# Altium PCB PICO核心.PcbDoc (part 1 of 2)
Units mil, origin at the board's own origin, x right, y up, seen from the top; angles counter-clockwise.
Board outline 3937.01 x 3543.31 mil, 4 copper layers (Top Layer, GND, VCC, Bottom Layer), stack 23.756 mil thick; 147 components, 105 nets, 477 pads, 202 vias.
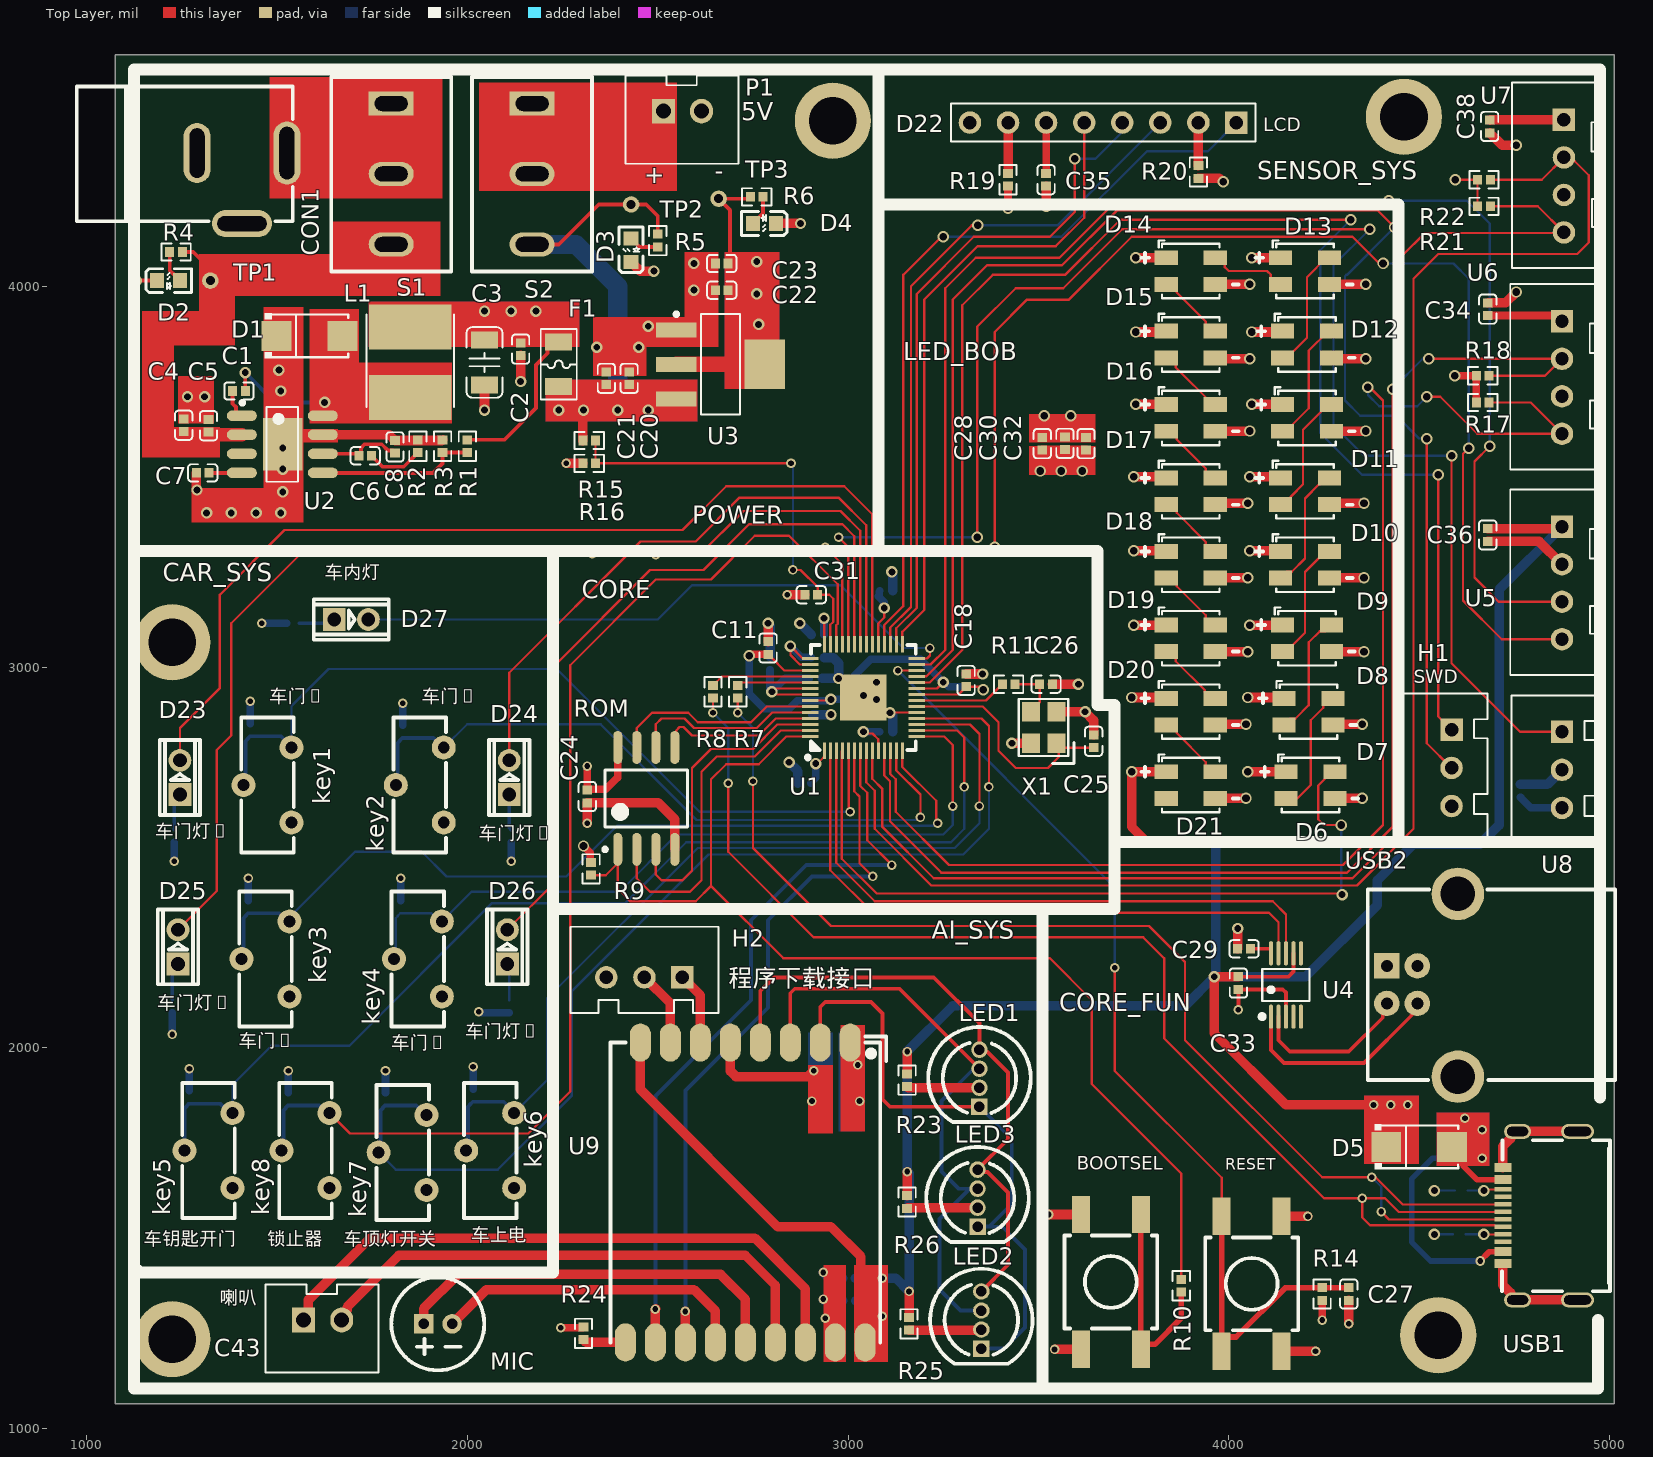
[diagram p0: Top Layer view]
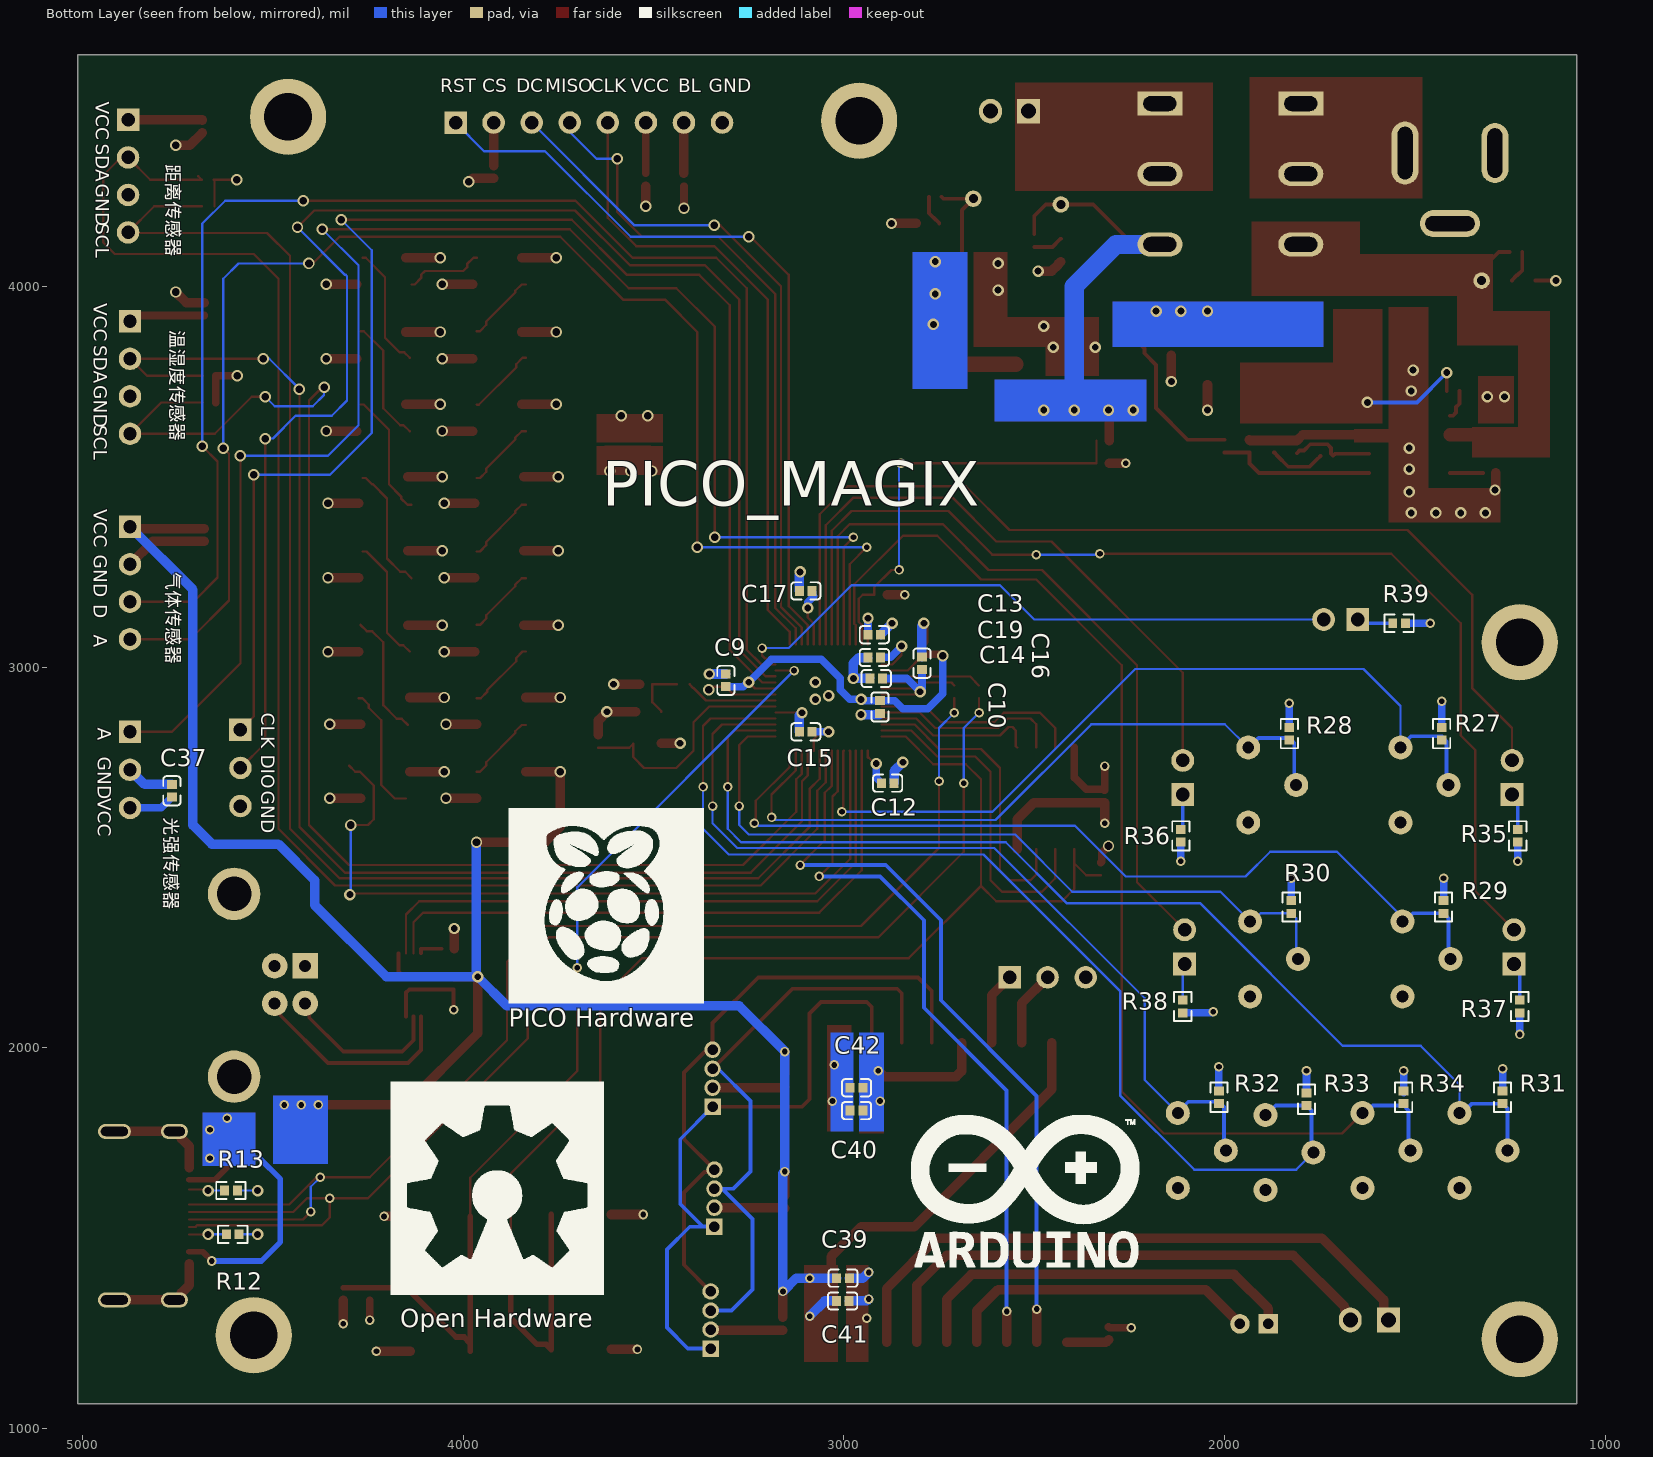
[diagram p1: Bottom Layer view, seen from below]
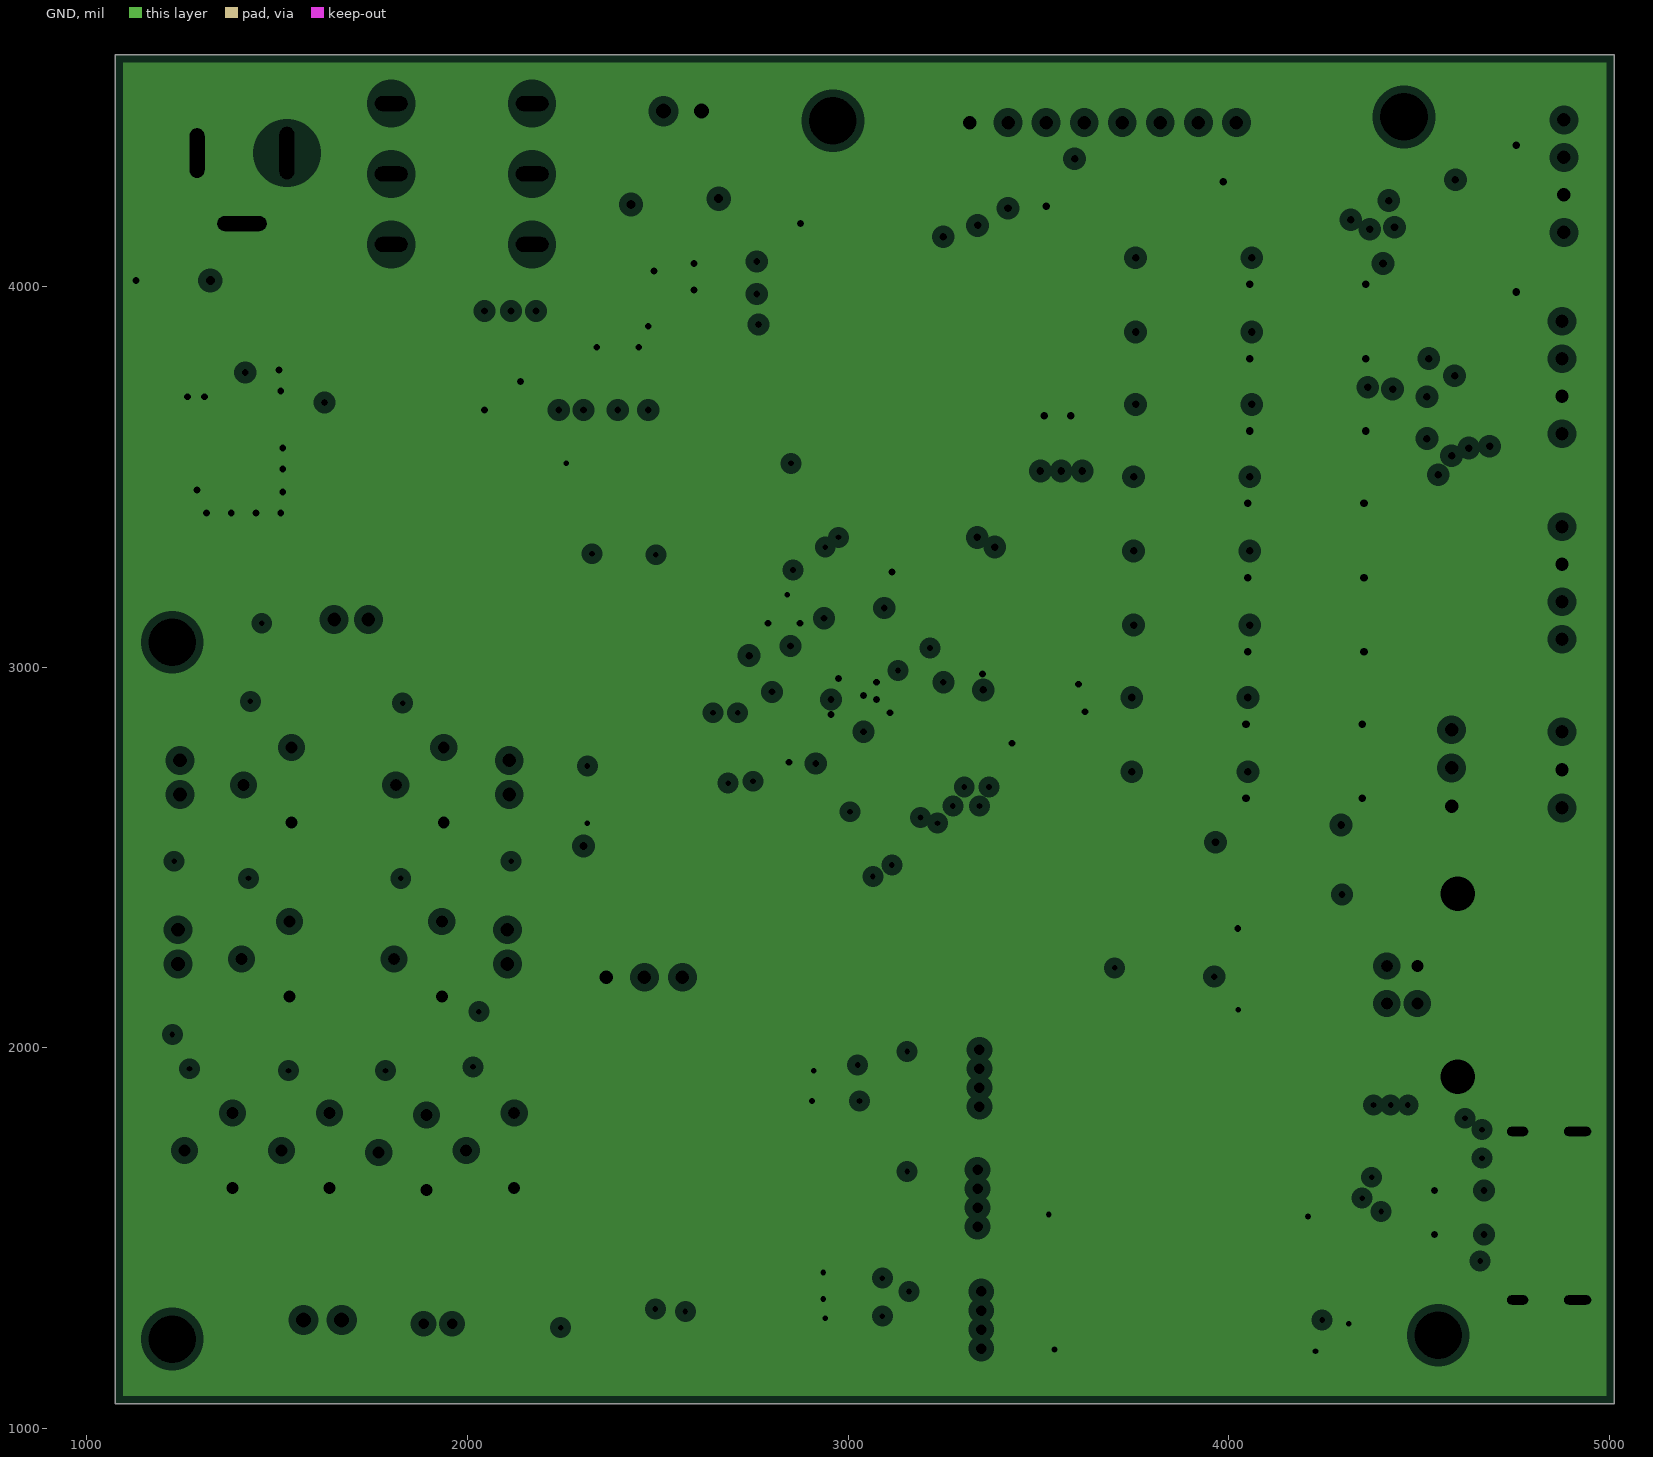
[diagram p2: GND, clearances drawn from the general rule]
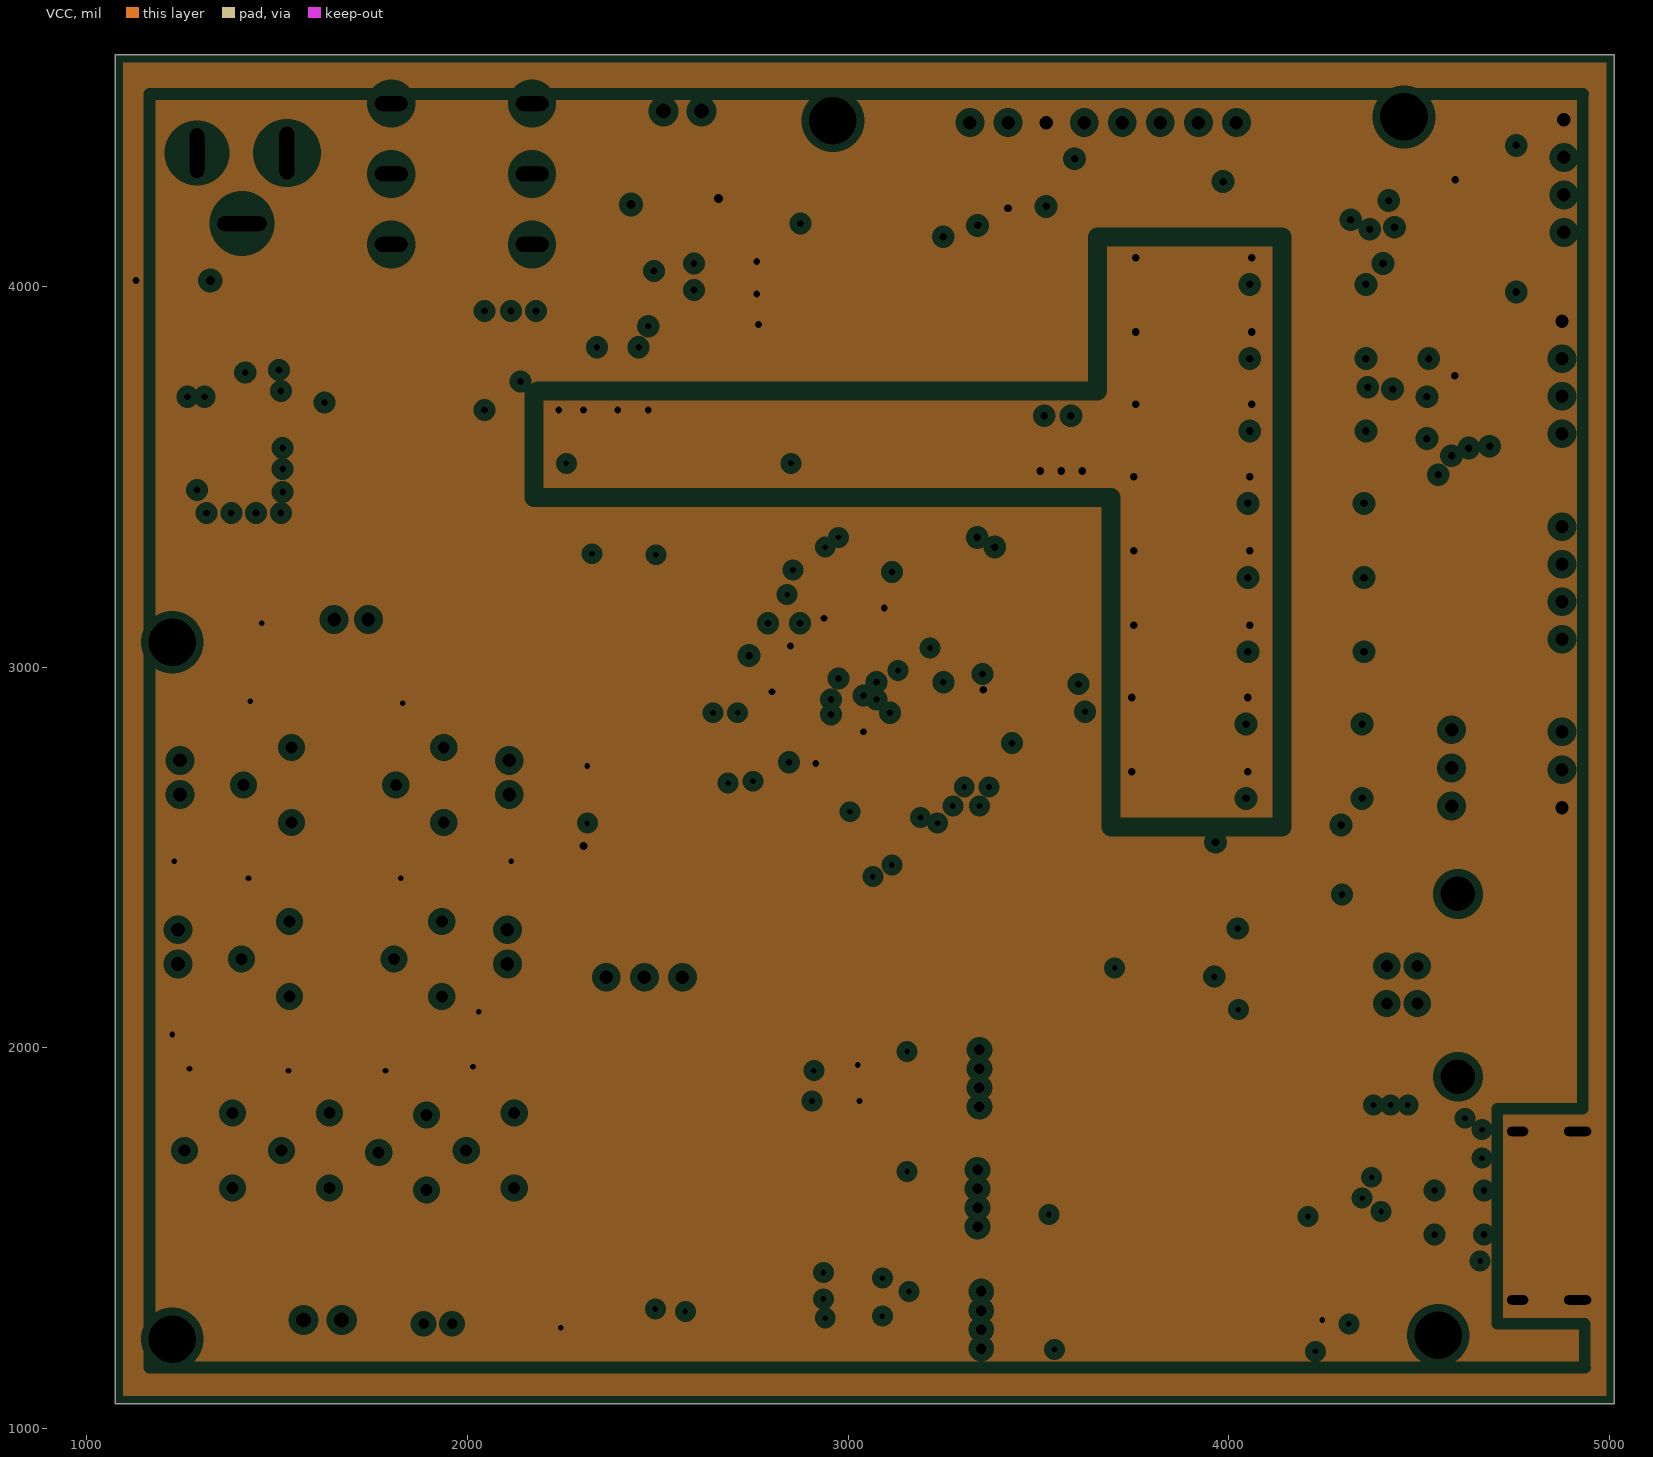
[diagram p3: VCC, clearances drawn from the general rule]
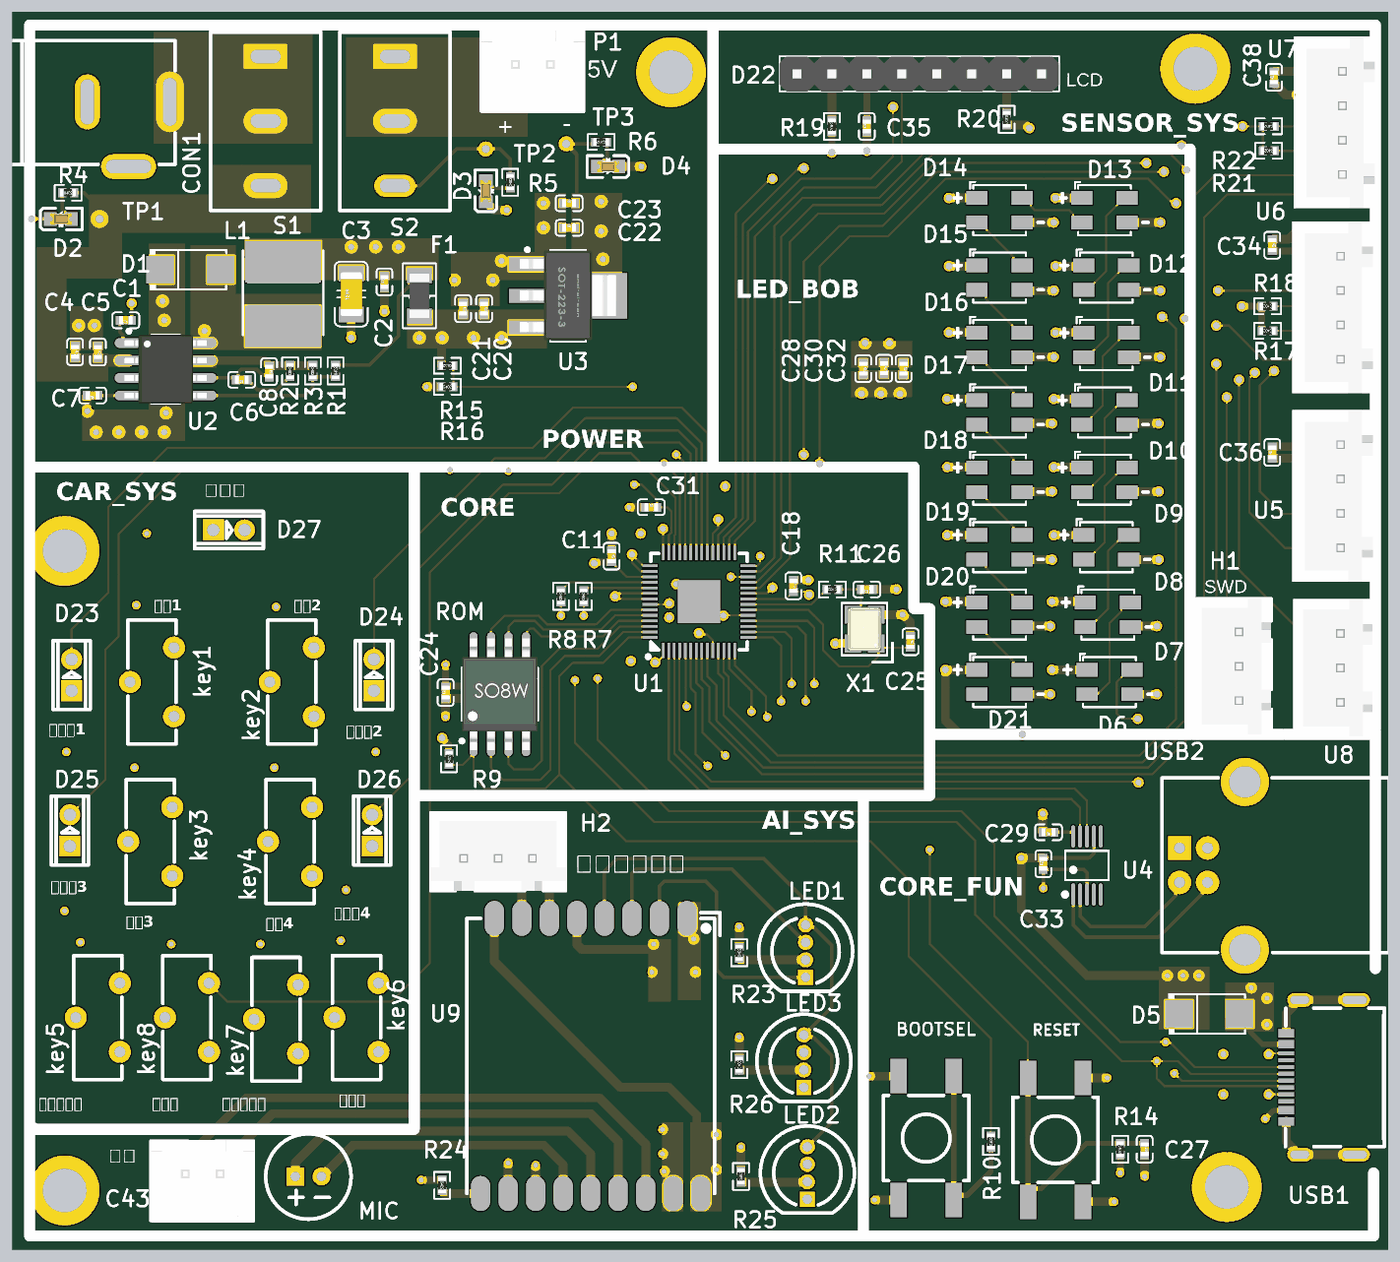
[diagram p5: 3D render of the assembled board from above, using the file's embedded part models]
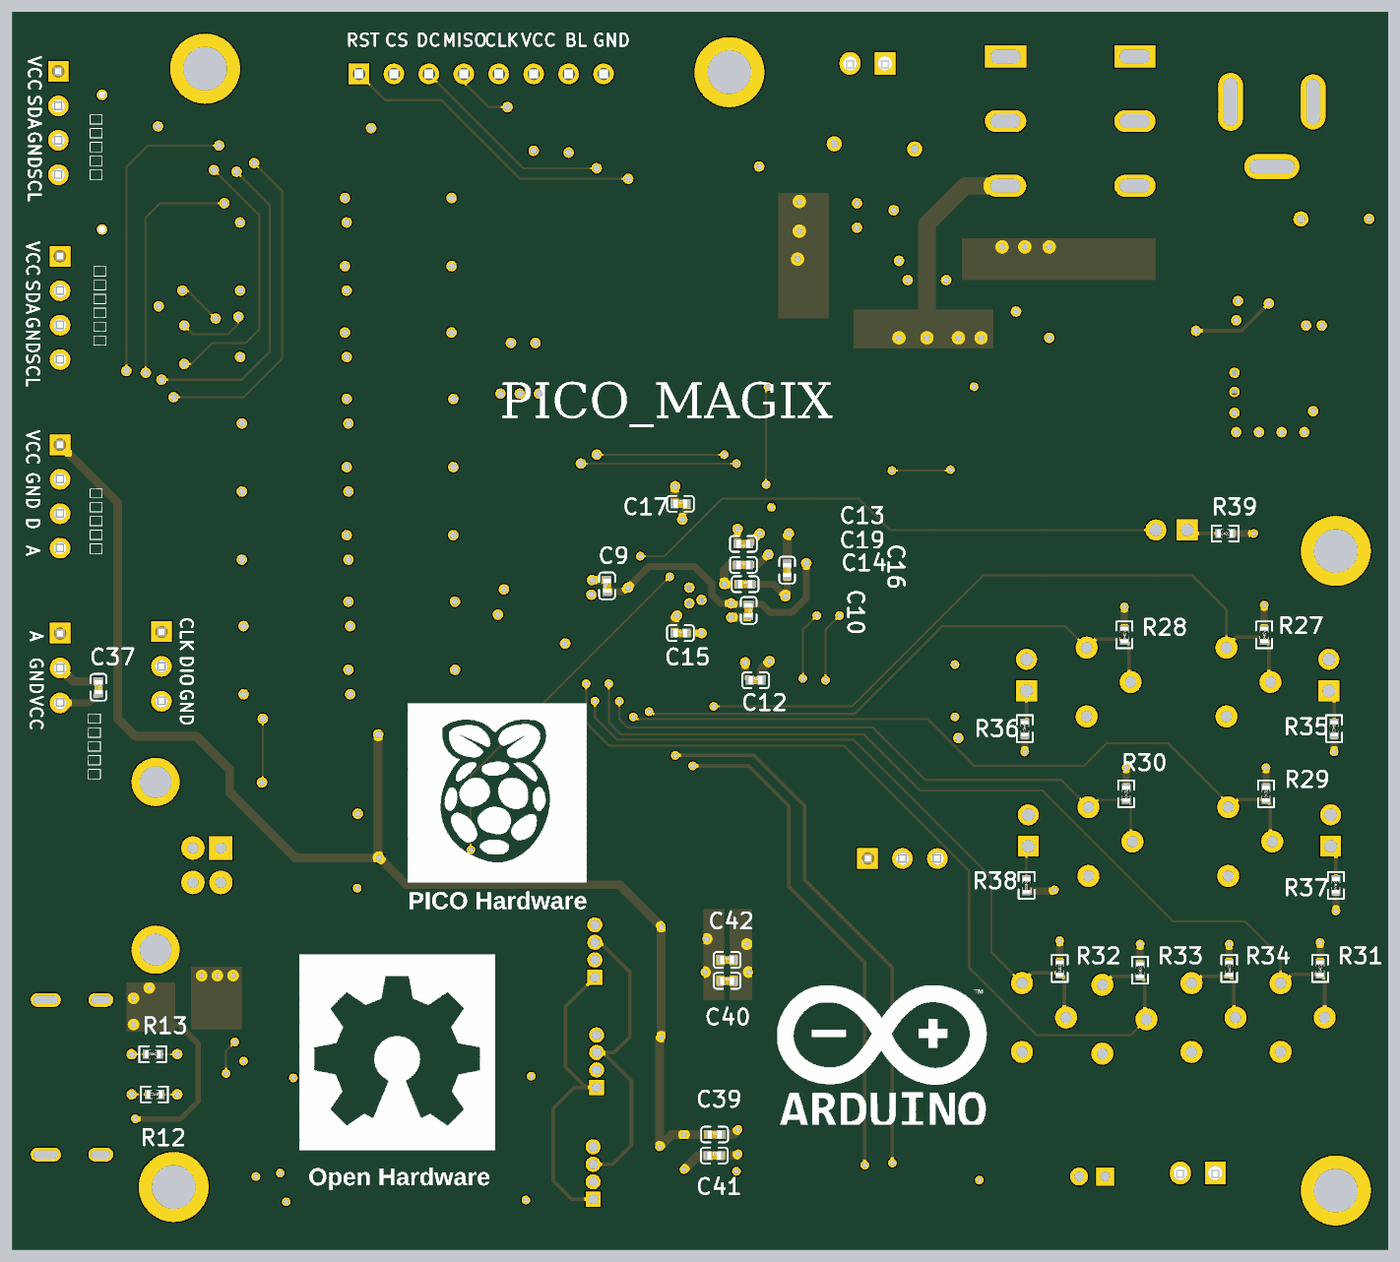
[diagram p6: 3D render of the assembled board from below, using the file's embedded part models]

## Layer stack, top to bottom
Top Solder: solder mask 0.4, Solder Resist, Dk 3.5
Top Layer: signal copper 1.4
Dielectric 2: prepreg 2.8, PP-006, Dk 4.1
GND: plane copper 1.3779, net GND
Dielectric 1: dielectric 12.6, FR-4, Dk 4.8
VCC: plane copper 1.3779, net (Multiple Nets)
Dielectric 3: prepreg 2.8, PP-006, Dk 4.1
Bottom Layer: signal copper 1.4
Bottom Solder: solder mask 0.4, Solder Resist, Dk 3.5

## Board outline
1075,1065 5012.01,1065 5012.01,4608.31 1075,4608.31

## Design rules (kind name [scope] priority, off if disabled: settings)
Clearance [All] p1: gap=6 ignorepadtopadclearanceinfootprint=FALSE
HoleSize [All] p1: absolutevalues=TRUE maxlimit=200 minlimit=1 maxpercent=80.000 minpercent=20.000
PlaneClearance [All] p1: clearance=20
PlaneConnect [All] p1: planeconnectstyle=Relief reliefexpansion=20 reliefentries=4 reliefconductorwidth=10 reliefairgap=10
PolygonConnect [All] p1: connectstyle=Relief reliefconductorwidth=10 reliefentries=4 polygonreliefangle="90 Angle" airgapwidth=10
RoutingVias [All] p1: holewidth=28 width=50 viastyle="Through Hole" minholewidth=28 minwidth=50 maxholewidth=28 maxwidth=50
SolderMaskExpansion [All] p1: expansion=4
Width [All] p1: maxlimit=100 minlimit=6 preferedwidth=10 minimp=50.000000 maximp=50.000000 favimp=50.000000
27 further rules are at their usual default settings.

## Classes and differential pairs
component class 车门车灯子系统: D23 D24 D25 D26 D27 key1 key2 key3 key4 key5 key6 key7 key8 R27 R28 R29 R30 R31 R32 R33 R34 R35 R36 R37 R38 R39
component class 语音识别系统: C39 C40 C41 C42 C43 H2 LED1 LED2 LED3 MIC R23 R24 R25 R26 U9
component class 环境监测系统: C34 C35 C36 C37 C38 D22 R17 R18 R19 R20 R21 R22 U5 U6 U7 U8
component class 传感器: C28 C29 C30 C31 C32 C33 D6 D7 D8 D9 D10 D11 D12 D13 D14 D15 D16 D17 D18 D19 D20 D21 R15 R16 U4 USB2
component class PICO核心: BOOTSEL C1 C2 C3 C4 C5 C6 C7 C8 C9 C10 C11 C12 C13 C14 C15 C16 C17 C18 C19 C20 C21 C22 C23 C24 C25 C26 C27 CON1 D1 D2 D3 D4 D5 F1 H1 L1 P1 R1 R2 R3 R4 R5 R6 R7 R8 R9 R10 R11 R12 R13 R14 RESET ROM S1 S2 TP1 TP2 TP3 U1 U2 U3 USB1 X1

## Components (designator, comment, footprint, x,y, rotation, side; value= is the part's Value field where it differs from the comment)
BOOTSEL "TSA343G00-250J2" SW-SMD_4P-L6.2-W6.3-P4.00-LS9.4 3690,1385 r270 top (schematic designator BOOTSEL1)
C1 "T_Cap_0603_0.1uF_25V_X5R" 0402_C 1400,3725 r180 top value=0.1uF,25V
C2 "T_Cap_1206_47uF_10V_X5R" 0402_C 2140,3835 r90 top value=10uF,10V
C3 "T_Cap_1206_47uF_10V_X5R" 1206_C 2045,3800 r90 top value=0.1uF,10V
C4 "T_Cap_0603_10uF_16V_X5R" 0402_C 1255,3635 r270 top value=10uF,16V
C5 "T_Cap_0603_0.1uF_25V_X5R" 0402_C 1320.14,3633.86 r270 top value=0.1uF,25V
C6 "4.7nF" 0402_C 1731.73,3555 r180 top
C7 "T_Cap_0603_10nF_50V_X7R" 0402_C 1305,3510 r180 top value=10nF,50V
C8 "39pF" 0402_C 1810,3578.27 r270 top
C9 "0.1u" 0402_C 3310,2965 r90 bottom
C10 "0.1u" 0402_C 2905,2895 r270 bottom
C11 "1u" 0402_C 2790,3050 r270 top
C12 "0.1u" 0402_C 2885,2695 r180 bottom
C13 "0.1u" 0402_C 2920,3085 r0 bottom
C14 "0.1u" 0402_C 2915,2970 r180 bottom
C15 "0.1u" 0402_C 3100,2830 r180 bottom
C16 "0.1u" 0402_C 2795,3010 r270 bottom
C17 "0.1u" 0402_C 3100,3200 r180 bottom
C18 "0.1u" 0402_C 3310,2965 r270 top
C19 "1u" 0402_C 2920,3025 r180 bottom
C20 "T_Cap_0603_10uF_16V_X5R" 0402_C 2425,3758.27 r270 top value=10uF,16V
C21 "T_Cap_0603_0.1uF_25V_X5R" 0402_C 2365,3758.27 r270 top value=0.1uF,25V
C22 "T_Cap_0603_10uF_16V_X5R" 0402_C 2668.27,3989.72 r0 top value=10uF,16V
C23 "T_Cap_0603_0.1uF_25V_X5R" 0402_C 2668.27,4060 r0 top value=0.1uF,25V
C24 "T_Cap_0603_0.1uF_25V_X5R" 0402_C 2315,2660 r90 top value=0.1uF,25V
C25 "15p" 0402_C 3645,2805 r270 top
C26 "15p" 0402_C 3520,2955 r180 top
C27 "T_Cap_0603_0.1uF_25V_X5R" 0402_C 4315,1353.27 r270 top value=0.1uF,25V
C28 "T_Cap_0603_0.1uF_25V_X5R" 0402_C 3510,3586.73 r270 top value=0.1uF,25V
C29 "10n" 0402_C 4040,2260 r180 top
C30 "T_Cap_0603_0.1uF_25V_X5R" 0402_C 3569.4,3587.58 r270 top value=47uF,25V
C31 "1n" 0402_C 2903.27,3190 r0 top
C32 "T_Cap_0603_0.1uF_25V_X5R" 0402_C 3625,3586.73 r270 top value=1uF,25V
C33 "T_Cap_0603_0.1uF_25V_X5R" 0402_C 4025,2170 r90 top value=0.1uF,25V
C34 "T_Cap_0603_0.1uF_25V_X5R" 0402_C 4680,3940 r270 top value=0.1uF,25V
C35 "T_Cap_0603_0.1uF_25V_X5R" 0402_C 3520,4280 r90 top value=0.1uF,25V
C36 "T_Cap_0603_0.1uF_25V_X5R" 0402_C 4680,3346.73 r90 top value=0.1uF,25V
C37 "T_Cap_0603_0.1uF_25V_X5R" 0402_C 4765,2675 r270 bottom value=0.1uF,25V
C38 "T_Cap_0603_0.1uF_25V_X5R" 0402_C 4685,4420 r90 top value=0.1uF,25V
C39 "T_Cap_0603_0.1uF_25V_X5R" 0402_C 3002.38,1395.03 r180 bottom value=10uF,25V
C40 "T_Cap_0603_0.1uF_25V_X5R" 0402_C 2966.73,1835 r180 bottom value=1uF,25V
C41 "T_Cap_0603_0.1uF_25V_X5R" 0402_C 3003.27,1335 r180 bottom value=0.1uF,25V
C42 "T_Cap_0603_0.1uF_25V_X5R" 0402_C 2966.73,1895 r180 bottom value=0.1uF,25V
C43 "spker" XH2.54A-2 1670,1285 r0 top
CON1 "3.5*1.3" DC-IN-TH_DC-005-5A-2.5 1408.11,4257.41 r0 top
D1 "T_SS34" SMA_L4.3-W2.6-LS5.2-RD 1585,3870 r0 top value=SS34
D2 "T_LED_Red_0805" 0603_LED 1214.68,4015 r0 top value=Red
D3 "T_LED_Red_0805" 0603_LED 2430,4094.68 r90 top value=Red
D4 "T_LED_Red_0805" 0603_LED 2780,4165 r180 top value=Red
D5 "1N4007W" SMA_L4.3-W2.6-LS5.2-RD 4500,1740 r0 top
D6 "WS2812" LED-SMD_4P-L3.5-W3.5-TL_WS2812B 4214.47,2689.96 r0 top
D7 "WS2812" LED-SMD_4P-L3.5-W3.5-TL_WS2812B 4209.47,2882.82 r0 top
D8 "WS2812" LED-SMD_4P-L3.5-W3.5-TL_WS2812B 4205,3075.69 r0 top
D9 "WS2812" LED-SMD_4P-L3.5-W3.5-TL_WS2812B 4200,3268.55 r0 top
D10 "WS2812" LED-SMD_4P-L3.5-W3.5-TL_WS2812B 4200,3461.41 r0 top
D11 "WS2812" LED-SMD_4P-L3.5-W3.5-TL_WS2812B 4205,3654.27 r0 top
D12 "WS2812" LED-SMD_4P-L3.5-W3.5-TL_WS2812B 4205,3847.14 r0 top
D13 "WS2812" LED-SMD_4P-L3.5-W3.5-TL_WS2812B 4200,4040 r0 top
D14 "WS2812" LED-SMD_4P-L3.5-W3.5-TL_WS2812B 3900,4040 r0 top
D15 "WS2812" LED-SMD_4P-L3.5-W3.5-TL_WS2812B 3900,3847.14 r0 top
D16 "WS2812" LED-SMD_4P-L3.5-W3.5-TL_WS2812B 3900,3654.27 r0 top
D17 "WS2812" LED-SMD_4P-L3.5-W3.5-TL_WS2812B 3900,3461.41 r0 top
D18 "WS2812" LED-SMD_4P-L3.5-W3.5-TL_WS2812B 3900,3268.55 r0 top
D19 "WS2812" LED-SMD_4P-L3.5-W3.5-TL_WS2812B 3900,3075.69 r0 top
D20 "WS2812" LED-SMD_4P-L3.5-W3.5-TL_WS2812B 3900,2882.82 r0 top
D21 "WS2812" LED-SMD_4P-L3.5-W3.5-TL_WS2812B 3900,2689.96 r0 top
D22 "st7735" HDR1X8 3670,4430 r180 top
D23 "T_LED_Red_0805" LED-TH_L5.0-W2.7-FD 1245,2710 r90 top value=Red
D24 "T_LED_Red_0805" LED-TH_L5.0-W2.7-FD 2110,2710 r90 top value=Red
D25 "T_LED_Red_0805" LED-TH_L5.0-W2.7-FD 1240,2265.12 r90 top value=Red
D26 "T_LED_Red_0805" LED-TH_L5.0-W2.7-FD 2105,2265.12 r90 top value=Red
D27 "T_LED_Red_0805" LED-TH_L5.0-W2.7-FD 1695.12,3125 r0 top value=yellow
F1 "16V 2A" 1206_FUSE 2240,3795 r270 top
H1 "HDR-F-2.54_1x3" XH2.54A-3 4585,2835 r270 top
H2 "HDR-F-2.54_1x3" XH2.54A-3 2565,2185 r180 top
key1 "TSA343G00-250J2" SW-TH_DEALON_MS-12D19-G2 1475,2690 r90 top
key2 "TSA343G00-250J2" SW-TH_DEALON_MS-12D19-G2 1875,2690 r90 top
key3 "TSA343G00-250J2" SW-TH_DEALON_MS-12D19-G2 1470,2233.43 r90 top
key4 "TSA343G00-250J2" SW-TH_DEALON_MS-12D19-G2 1870,2233.43 r90 top
key5 "TSA343G00-250J2" SW-TH_DEALON_MS-12D19-G2 1320,1730 r90 top
key6 "TSA343G00-250J2" SW-TH_DEALON_MS-12D19-G2 2060,1730 r90 top
key7 "TSA343G00-250J2" SW-TH_DEALON_MS-12D19-G2 1830,1725 r90 top
key8 "TSA343G00-250J2" SW-TH_DEALON_MS-12D19-G2 1575,1730 r90 top
L1 "6.8uH" IND-SMD_L5.8-W5.2 1850,3800 r270 top
LED1 "RGB-3528" LED-TH_4P-BD6.9-P1.27-R 3345,1920 r270 top
LED2 "RGB-3528" LED-TH_4P-BD6.9-P1.27-R 3350,1285 r270 top
LED3 "RGB-3528" LED-TH_4P-BD6.9-P1.27-R 3340,1605 r270 top
MIC "咪头" MIC-TH_BD6.0-P1.90-D0.4-L-RD 1922.4,1275 r0 top (schematic designator m1)
P1 "Header 2H" XH2.54A-2 2615,4460 r0 top
R1 "T_Res_0603_10k_1%_1/10W" 0402_R 2000,3580 r90 top value=10k
R2 "49.9k" 0402_R 1870,3580 r270 top
R3 "1.91k" 0402_R 1935,3580 r270 top
R4 "T_Res_0603_10k_1%_1/10W" 0402_R 1235,4090 r0 top value=10k
R5 "T_Res_0603_10k_1%_1/10W" 0402_R 2500,4120 r90 top value=10k
R6 "T_Res_0603_4.3k_5%_1/10W" 0402_R 2760,4235 r180 top value=4.3k
R7 "27" 0402_R 2710,2935 r270 top
R8 "27" 0402_R 2645,2935 r270 top
R9 "DNF（不装）" 0402_R 2325,2470 r90 top
R10 "1k" 0402_R 3875,1375 r90 top
R11 "1k" 0402_R 3421.73,2955 r180 top
R12 "1k" 0402_R 4605,1510 r0 bottom
R13 "1k" 0402_R 4610,1625 r0 bottom
R14 "10k" 0402_R 4245,1353.27 r270 top
R15 "200k" 0402_R 2320,3595 r180 top
R16 "100k" 0402_R 2320,3535 r0 top
R17 "1k" 0402_R 4666.73,3694.72 r180 top
R18 "1k" 0402_R 4666.73,3765 r180 top
R19 "1k" 0402_R 3420,4280 r270 top
R20 "10k" 0402_R 3920,4300 r270 top
R21 "1k" 0402_R 4670,4210 r180 top
R22 "1k" 0402_R 4670,4280 r180 top
R23 "100r" 0402_R 3155,1915 r90 top
R24 "4.7k" 0402_R 2305,1250 r270 top
R25 "100r" 0402_R 3160,1275 r90 top
R26 "100r" 0402_R 3155,1595 r90 top
R27 "T_Res_0603_4.3k_5%_1/10W" 0402_R 1430,2825 r90 bottom value=4.3k
R28 "T_Res_0603_4.3k_5%_1/10W" 0402_R 1830,2825 r90 bottom value=4.3k
R29 "T_Res_0603_4.3k_5%_1/10W" 0402_R 1425,2370 r90 bottom value=4.3k
R30 "T_Res_0603_4.3k_5%_1/10W" 0402_R 1825,2370 r90 bottom value=4.3k
R31 "T_Res_0603_4.3k_5%_1/10W" 0402_R 1270,1870 r90 bottom value=4.3k
R32 "T_Res_0603_4.3k_5%_1/10W" 0402_R 2015,1870 r90 bottom value=4.3k
R33 "T_Res_0603_4.3k_5%_1/10W" 0402_R 1785,1865 r90 bottom value=4.3k
R34 "T_Res_0603_4.3k_5%_1/10W" 0402_R 1530,1870 r90 bottom value=4.3k
R35 "T_Res_0603_4.3k_5%_1/10W" 0402_R 1230,2556.73 r270 bottom value=4.3k
R36 "T_Res_0603_4.3k_5%_1/10W" 0402_R 2115,2556.73 r270 bottom value=4.3k
R37 "T_Res_0603_4.3k_5%_1/10W" 0402_R 1225,2108.27 r270 bottom value=4.3k
R38 "T_Res_0603_4.3k_5%_1/10W" 0402_R 2110,2108.27 r270 bottom value=4.3k
R39 "T_Res_0603_4.3k_5%_1/10W" 0402_R 1541.73,3115 r180 bottom value=4.3k
RESET "TSA343G00-250J2" SW-SMD_4P-L6.2-W6.3-P4.00-LS9.4 4060,1380 r270 top (schematic designator RESET1)
ROM "W25Q16JVSSIQ" SOIC8-208mil 2470,2655 r90 top (schematic designator ROM1)
S1 "SS-12F23" SW-TH_MT-0-103-A101-M200-RS 1800,4295 r270 top
S2 "SS-12F23" SW-TH_MT-0-103-A101-M200-RS 2170,4295 r270 top
TP1 "T_TestPoint_H" TP_H 1325,4015 r0 top
TP2 "T_TestPoint_H" TP_H 2430,4215 r90 top
TP3 "T_TestPoint_H" TP_H 2660,4230 r180 top
U1 "PICO" LQFN-56_L7.0-W7.0-P0.4-EP 3040,2920 r90 top
U2 "TPS54331DR" SOIC8E 1515,3585 r0 top
U3 "T_AMS1117-3.3V" SOT223 2665,3795 r0 top value=AMS1117-3.3V
U4 "CH340E" MSOP-10_L3.0-W3.0-P0.50-LS5.0-BL 4150,2165 r0 top
U5 "气体传感器" XH2.54A-4 4875,3368.43 r270 top
U6 "AHT21B" XH2.54A-4 4875,3907.9 r270 top
U7 "VL6180X" XH2.54A-4 4880,4436.85 r270 top
U8 "TEMT6000" XH2.54A-3 4875,2830 r270 top
U9 "CI-C22GS02S" SMD-17_L20.0-W1.80-CI-C22GS02S 2730,1620 r270 top
USB1 "TYPEC-302-BRP16SC08" USB-C-SMD_TYPEC-302-BRP16SC08 4817.94,1559.02 r90 top
USB2 "MICROUSB FEMALE" USB-B/S_A 4495,2165.79 r90 top
X1 "12MHz" "OSC 3225-4P" 3513.46,2841.34 r90 top

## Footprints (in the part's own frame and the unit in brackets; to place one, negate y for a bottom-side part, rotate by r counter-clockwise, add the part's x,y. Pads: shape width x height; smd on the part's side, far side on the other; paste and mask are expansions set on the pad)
0402_C [mm]
  rect 0.6x0.65 smd mask+0.051: 1(-0.425,0) 2(0.425,0)
  silkscreen extent -0.97,-0.58 0.97,0.58, body extent -0.5,-0.3 0.5,0.3, height 0.2
0402_R [mm]
  rect 0.6x0.65 smd mask+0.051: 1(-0.425,0) 2(0.425,0)
  silkscreen extent -0.97,-0.58 0.97,0.58, body extent -0.57,-0.27 0.58,0.28, height 0.41
0603_LED [mm]
  rect 0.93x0.98 smd: 1(0.77,0) 2(-0.77,0)
  silkscreen extent -1.5,-0.79 1.54,0.79, body extent -0.8,-0.4 0.8,0.4, height 0.6
1206_C [mm]
  rect 1.13x1.8 smd: 1(-1.49,0) 2(1.49,0)
  silkscreen extent -2.36,-1.2 2.35,1.2, body extent -1.6,-0.81 1.6,0.79, height 1
1206_FUSE [mm]
  rect 1.13x1.8 smd: 1(-1.49,0) 2(1.49,0)
  silkscreen extent -2.36,-1.2 2.35,1.2, body extent -1.6,-0.73 1.6,0.73, height 1.63
DC-IN-TH_DC-005-5A-2.5 [mm]
  oval 1.8x4.2 hole 1 slot 3.5 at 90 deg: 1(3,2.352)
  oval 1.8x4 hole 1 slot 3.3 at 90 deg: 2(-3,2.352)
  oval 4x1.8 hole 1 slot 3.3 at 0 deg: 3(0,-2.352)
  silkscreen extent -11.03,-2.2 3.38,6.81
HDR1X8 [mm] "Connector; Header; 8 Position"
  rect 1.5x1.5 hole 0.9: 1(-8.89,0)
  round 1.5 hole 0.9: 2(-6.35,0) 3(-3.81,0) 4(-1.27,0) 5(1.27,0) 6(3.81,0) 7(6.35,0) 8(8.89,0)
  silkscreen extent -10.16,-1.27 10.16,1.27, body extent -10.16,-1.27 10.16,1.27, height 8.54
IND-SMD_L5.8-W5.2 [mm]
  rect 3x5.5 smd: 1(2.35,0) 2(-2.351,0)
  silkscreen extent -3.17,-2.92 2.98,2.92
LED-SMD_4P-L3.5-W3.5-TL_WS2812B [mm]
  rect 1.545x0.997 smd: 1(-1.638,0.89) 2(-1.638,-0.89) 3(1.638,-0.89) 4(1.638,0.89)
  silkscreen extent -3.3,-1.82 3.17,2.04
LED-TH_4P-BD6.9-P1.27-R [mm]
  rect 1.1x1.1 hole 0.7: 1(1.905,0)
  round 1.1 hole 0.7: 2(0.635,0) 3(-0.635,0) 4(-1.905,0)
  silkscreen extent -3.42,-3.42 2.92,3.42
LED-TH_L5.0-W2.7-FD [mil]
  rect 60x60 hole 36: 1(-44.88,0)
  round 60 hole 36: 2(44.88,0)
  silkscreen extent -98,-53 98,53
LQFN-56_L7.0-W7.0-P0.4-EP [mm]
  rect 1.1x0.2 smd: 1(-3.55,2.6) 2(-3.55,2.2) 3(-3.55,1.8) 4(-3.55,1.4) 5(-3.55,1) 6(-3.55,0.6) 7(-3.55,0.2) 8(-3.55,-0.2) 9(-3.55,-0.6) 10(-3.55,-1) 11(-3.55,-1.4) 12(-3.55,-1.8) 13(-3.55,-2.2) 14(-3.55,-2.6) 29(3.55,-2.6) 30(3.55,-2.2) 31(3.55,-1.8) 32(3.55,-1.4) 33(3.55,-1) 34(3.55,-0.6) 35(3.55,-0.2) 36(3.55,0.2) 37(3.55,0.6) 38(3.55,1) 39(3.55,1.4) 40(3.55,1.8) 41(3.55,2.2) 42(3.55,2.6)
  rect 0.2x1.1 smd: 15(-2.6,-3.55) 16(-2.2,-3.55) 17(-1.8,-3.55) 18(-1.4,-3.55) 19(-1,-3.55) 20(-0.6,-3.55) 21(-0.2,-3.55) 22(0.2,-3.55) 23(0.6,-3.55) 24(1,-3.55) 25(1.4,-3.55) 26(1.8,-3.55) 27(2.2,-3.55) 28(2.6,-3.55) 43(2.6,3.55) 44(2.2,3.55) 45(1.8,3.55) 46(1.4,3.55) 47(1,3.55) 48(0.6,3.55) 49(0.2,3.55) 50(-0.2,3.55) 51(-0.6,3.55) 52(-1,3.55) 53(-1.4,3.55) 54(-1.8,3.55) 55(-2.2,3.55) 56(-2.6,3.55)
  rect 3.1x3.1 smd: 57(0,0)
  silkscreen extent -4.13,-3.5 3.5,3.83
MIC-TH_BD6.0-P1.90-D0.4-L-RD [mm]
  rect 1.3x1.3 hole 0.7: 1(-0.95,0)
  round 1.3 hole 0.7: 2(0.95,0)
  silkscreen extent -3.1,-3.1 3.1,3.1
MSOP-10_L3.0-W3.0-P0.50-LS5.0-BL [mm]
  oval 0.28x1.62 smd: 1(-1,-2.11) 2(-0.5,-2.11) 3(0,-2.11) 4(0.5,-2.11) 5(1,-2.11) 6(1,2.11) 7(0.5,2.11) 8(0,2.11) 9(-0.5,2.11) 10(-1,2.11)
  silkscreen extent -1.74,-2.26 1.58,1.07
"OSC 3225-4P" [mm] "3.2*2.5*0.7mm(长宽高)"
  rect 1.3x1.2 smd: 1(-1.05,-0.85) 2(1.05,-0.85) 3(1.05,0.85) 4(-1.05,0.85)
  silkscreen extent -2.41,-2.03 1.91,1.65, body extent -1.6,-1.25 1.6,1.25, height 0.7
SMA_L4.3-W2.6-LS5.2-RD [mm]
  rect 2x2 smd: 1(-2.2,0) 2(2.2,0)
  silkscreen extent -2.98,-1.5 2.6,1.5
SMD-17_L20.0-W1.80-CI-C22GS02S [mm]
  oval 2.54x1.4 smd: 1(-10,7) 2(-10,5) 3(-10,3) 4(-10,1) 5(-10,-1) 6(-10,-3) 7(-10,-5) 8(-10,-7) 9(10,-8) 10(10,-6) 11(10,-4) 12(10,-2) 13(10,0) 14(10,2) 15(10,4) 16(10,6) 17(10,8)
  silkscreen extent -10.41,-9 10,9.4
SOIC8-208mil [mm] "SOIC8, 208mil, 8-Leads, Body 5.28x5.28mm, Pitch 1.27mm"
  oval 2.2x0.6 smd: 1(-3.4,1.905) 2(-3.4,0.635) 3(-3.4,-0.635) 4(-3.4,-1.905) 5(3.4,-1.905) 6(3.4,-0.635) 7(3.4,0.635) 8(3.4,1.905)
  silkscreen extent -3.52,-2.75 1.9,2.88, body extent -4.05,-2.73 4.05,2.73, height 1.75
SOIC8E [mm]
  oval 2x0.7 smd: 1(-2.725,1.905) 2(-2.725,0.635) 3(-2.725,-0.635) 4(-2.725,-1.905) 5(2.675,-1.905) 6(2.675,-0.635) 7(2.675,0.635) 8(2.675,1.905)
  rect 2.62x3.51 smd: 9(0,0)
  silkscreen extent -2.82,-2.5 1.02,2.89, body extent -3.03,-2.5 2.97,2.5, height 1.75
SOT223 [mm] "SOT223, 4-Leads, Body 6.50x7.00mm (avg), Pitch 2.30mm, IPC Low Density"
  rect 2.7x1 smd: 1(-2.95,2.3) 2(-2.95,0) 3(-2.95,-2.3)
  rect 2.7x3.3 smd: 4(2.95,0)
  silkscreen extent -3.07,-3.35 1.3,3.47, body extent -3.5,-3.22 3.5,3.28, height 1.7
SW-SMD_4P-L6.2-W6.3-P4.00-LS9.4 [mm]
  rect 2.5x1.2 smd: 1(-4.5,-2) 1(4.5,-2) 2(-4.5,2) 2(4.5,2)
  silkscreen extent -3.1,-3.1 3.1,3.1
SW-TH_DEALON_MS-12D19-G2 [mm]
  round 1.6 hole 0.8: 1(-2.5,-1.6) 2(0,1.6) 2(2.5,-1.6)
  silkscreen extent -4.5,-1.75 4.5,1.75
SW-TH_MT-0-103-A101-M200-RS [mm]
  rect 1.6x3 hole 1 slot 2.2 at 90 deg: 1(-4.7,0)
  oval 1.6x3 hole 1 slot 2.2 at 90 deg: 2(0,0) 3(4.7,0)
  silkscreen extent -6.48,-4 6.5,4
TP_H [mm] "测试点-过孔"
  round 1.1 hole 0.6: 1(0,0)
USB-B/S_A [mm] "b型USB 母座 16.3*13.7*11mm"
  round 3.5 hole 2.3: 0(-6.141,-2.71) 5(6.051,-2.71)
  rect 1.7x1.7 hole 0.8: 1(1.25,2.032)
  round 1.7 hole 0.8: 2(-1.25,2.032) 3(-1.25,0) 4(1.25,0)
  silkscreen extent -6.35,-13.21 6.35,3.3, body extent -6.86,-13.16 6.86,3.14, height 11.45
USB-C-SMD_TYPEC-302-BRP16SC08 [mm]
  rect 0.6x1.15 smd: 1(-3.2,2.488) 2(-2.4,2.488) 11(2.4,2.488) 12(3.2,2.488)
  rect 0.3x1.15 smd: 3(-1.75,2.488) 4(-1.25,2.488) 5(-0.75,2.488) 6(-0.25,2.488) 7(0.25,2.488) 8(0.75,2.488) 9(1.25,2.488) 10(1.75,2.488)
  oval 1x1.8 hole 0.61 slot 1.4 at 90 deg: 13(-5.62,1.513) 14(5.62,1.513)
  oval 1x2.2 hole 0.61 slot 1.8 at 90 deg: 15(-5.62,-2.487) 16(5.62,-2.487)
  silkscreen extent -5.03,-4.65 5.03,2.55
XH2.54A-2 [mil]
  rect 60x65 hole 39.37: 1(-100.1,0)
  oval 60x65 hole 39.37: 2(0,0)
  silkscreen extent -200,-138 97,93, body extent -198,-142 98,94, height 276
XH2.54A-3 [mm]
  rect 1.5x1.5 hole 0.9: 1(0,0)
  round 1.5 hole 0.9: 2(2.54,0) 3(5.08,0)
  silkscreen extent -2.41,-3.38 7.47,2.39, body extent -2.41,-3.41 7.49,2.34, height 7
XH2.54A-4 [mm]
  rect 1.5x1.5 hole 0.9: 1(0,0)
  round 1.5 hole 0.9: 2(2.5,0) 3(5,0) 4(7.5,0)
  silkscreen extent -2.49,-3.45 9.88,2.49, body extent -2.47,-3.38 9.93,2.37, height 7

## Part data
BOOTSEL key1 key2 key3 key4 key5 key6 key7 key8 RESET: BOM_JLCPCB Part Class="Extended Part", BOM_Manufacturer=BRIGHT
C1 C5 C21 C23 C24 C27 C28 C30 C32 C33 C34 C35 C36 C37 C38 C39 C40 C41 C42: "贴片电容", Tolerance=10%, Withstand Voltage=25V
C2 C3: "贴片电容", Tolerance=10%, Withstand Voltage=10V
C4 C20 C22: "贴片电容", Tolerance=10%, Withstand Voltage=16V
C6 C8: library part Cap
C7: "贴片电容", Tolerance=10%, Withstand Voltage=50V
C11 C19: library part 0.1u
C26: Package Display=No
C43: library part SPK
CON1: library part P-DC, "低压电源接口"
D1: "肖特基二极管"
D2 D3 D4 D23 D24 D25 D26 D27: "红色LED灯"
D5: BOM_Manufacturer="BLUE ROCKET"
F1: library part Fuse
L1: library part Inductor
LED1 LED2 LED3: library part LED-RGB-3528, "三基色LED"
MIC: library part mic
P1: "Header, 2-Pin, Right Angle"
R1 R4 R5: "贴片电阻", Power=1/10W, Tolerance=1%
R2 R3: library part Res
R6 R27 R28 R29 R30 R31 R32 R33 R34 R35 R36 R37 R38 R39: "贴片电阻", Power=1/10W, Tolerance=5%
R14 R20: library part 1k
R23 R24 R25 R26: library part 100k
ROM: BOM_JLCPCB Part Class="Extended Part", BOM_Manufacturer=WINBOND
S1 S2: library part SSW-1P, "1路波动开关"
TP1 TP2 TP3: "测试点_过孔"
U1: library part PICO_CORE
U2: library part TPS54331, "TI, 3A, 3.5-28V, Buck"
U3: "电源芯片"
U4: BOM_JLCPCB Part Class="Extended Part", BOM_Manufacturer=WCH
U5: library part MQ135
U9: BOM_JLCPCB Part Class="Extended Part", BOM_Manufacturer=Chiplntelli(启?
USB1: BOM_Manufacturer=XUNPU(Ѷ?
USB2: BOM_JLCPCB Part Class="Extended Part", BOM_Manufacturer=ValuePro, BOM_Manufacturer Part="micro USBFemale"
X1: BOM_JLCPCB Part Class="Extended Part", BOM_Manufacturer=YXC, BOM_Manufacturer Part=X322512MLB4SI

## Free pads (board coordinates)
  round 200 hole 125: 1(1225,1235) 1(1225,3065) 1(2960,4435) 1(4460,4445) 1(4550,1245)

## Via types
v1: diameter 25, hole 15, Top Layer to Bottom Layer, 71 vias
v2: diameter 30, hole 20, Top Layer to Bottom Layer, 68 vias
v3: diameter 30, hole 18, Top Layer to Bottom Layer, 63 vias

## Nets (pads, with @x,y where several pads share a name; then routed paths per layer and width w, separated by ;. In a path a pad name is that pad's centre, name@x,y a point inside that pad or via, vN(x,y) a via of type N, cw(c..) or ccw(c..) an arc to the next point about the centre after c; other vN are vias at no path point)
1V1: C9.1 C10.1 C11.2 U1.23 U1.45 U1.50 | length 1100.3
  Top Layer w6: C11.2@2790,3033.27 2790.98,3033.27 2799.8,3024.46 2799.8,3023.47 2832.4,2990.87 U1.45@2900.24,2990.87 ; U1.50@2900.24,2912.13 2952.13,2912.13 v3(2954.94,2914.94) ; U1.23@3179.76,2943.62 3233.62,2943.62 v3(3250,2960)
  Top Layer w20: v2(2740,3030) 2743.27,3033.27 C11.2@2790,3033.27
  Bottom Layer w20: v2(2740,3030) 2740,2930 2780,2890 2845,2890 2866.73,2911.73 C10.1@2905,2911.73 2949.03,2911.73 2952.23,2914.94 v3(2954.94,2914.94) 2984.94,2914.94 3010,2940 3010,2970 3060,3020 3190,3020 v3(3250,2960) 3252.71,2960 3264.44,2948.27 C9.1@3310,2948.27
3V3: C12.1 C13.2 C14.2 C15.2 C16.2 C17.2 C18.2 C19.2 C22.2 C23.2 C24.2 C34.2 C35.2 C37.2 C38.2 C40.1 C42.1 D22.6 R6.2 R9.2 R14.2 R17.2 R18.2 R19.2 R21.2 R22.2 R24.1 R27.2 R28.2 R29.2 R30.2 R31.2 R32.2 R33.2 R34.2 R35.2 R36.2 R37.2 R38.2 R39.2 ROM.8 TP3.1 U1.1 U1.10 U1.22 U1.33 U1.42 U1.43 U1.44 U1.48 U1.49 U3.2 U3.4 U6.1 U7.1 U8.3 U9.1 | length 3918.6
  Top Layer w6: v3@2848.43,3040.2 2848.43,3031.3 2873.11,3006.61 U1.44@2900.24,3006.61 ; v3(2848.43,3055) 2880.13,3023.3 2899.3,3023.3 U1.43@2900.24,3022.36 ; U1.49@2900.24,2927.87 2802.87,2927.87 2802.87,2943.62 U1.48@2900.24,2943.62 ; v3(2915,2746.3) 2919.73,2746.3 2935.01,2761.58 2936.7,2761.58 2937.64,2762.52 U1.1@2937.64,2780.24 ; v3(2936.73,3128.27) 2937.64,3127.36 U1.42@2937.64,3059.76 ; v3(3040,2830) 3044.59,2825.41 3064.03,2825.41 3079.37,2810.07 U1.10@3079.37,2780.24 ; U1.33@3079.37,3059.76 3079.37,3114.37 3095,3130 v3(3095,3155) ; U1.22@3179.76,2927.87 3289.61,2927.87 3300.2,2938.47 3300.2,2939.46 3309.02,2948.27 C18.2@3310,2948.27 3346.73,2948.27 v2(3355,2940) ; v2(4595,4280) R22.2@4653.27,4280 ; R21.2@4653.27,4210 4653.27,4278.27 R22.2@4655,4280 ; C38.2@4683.27,4435 C38.2@4685,4436.73
  Top Layer w10: 2690,4080 2690,4200 TP3.1@2660,4230 2738.27,4230 R6.2@2743.27,4235
  Top Layer w20: v1(2245,1265) 2303.27,1265 R24.1@2305,1266.73 ; v2(2305,2530) 2323.12,2511.88 2323.12,2488.54 2324.93,2486.73 R9.2@2325,2486.73 ; v1(2315,2740) C24.2@2315,2676.73 2315.98,2676.73 2317.8,2678.54 2363.54,2678.54 2395,2710 ROM.8@2395,2788.86 ; v3@2846.51,3056.91 v3(2848.43,3055) ; v2(3420,4205) R19.2@3420,4263.27 ; C35.2@3520,4296.73 D22.6@3520,4430 ; v1(4245,1285) R14.2@4245,1336.54 ; v2@4592.58,3765.31 v2(4592.89,3765) R18.2@4650,3765 R17.2@4650,3694.72 ; C34.2@4680,3923.27 4859.63,3923.27 U6.1@4875,3907.9
  Top Layer w25: C38.2@4685,4436.73 4685.12,4436.85 U7.1@4880,4436.85
  Top Layer w40: U3.2@2548.86,3795 U3.4@2781.14,3795 U3.4@2759.09,3817.05
  Bottom Layer w20: v1(1225,2035) R37.2@1225,2091.54 ; v1(1230,2490) R35.2@1230,2540 ; R31.2@1270,1886.73 v1(1270,1945) ; R29.2@1425,2386.73 v1(1425,2445) ; R27.2@1430,2851.73 v1(1430,2910) ; v1(1460,3115) R39.2@1525,3115 ; R34.2@1530,1881.73 v1(1530,1940) ; R33.2@1785,1881.73 v1(1785,1940) ; R30.2@1825,2386.73 v1(1825,2445) ; R28.2@1830,2846.73 v1(1830,2905) ; R32.2@2015,1891.73 v1(2015,1950) ; v1(2030,2095) 2033.46,2091.54 R38.2@2110,2091.54 ; v1(2115,2490) R36.2@2115,2540 ; C16.2@2795,2993.27 2795,2942.71 2800,2937.71 v3(2800,2935) 2835,2970 C14.2@2898.27,2970 ; v3(2848.43,3055) 2877.33,3026.1 2902.17,3026.1 C19.2@2903.27,3025 ; C12.1@2901.73,2695 2901.73,2695.98 2915,2709.25 v3(2915,2746.3) ; C13.2@2936.73,3085 v3(2936.73,3128.27) ; v3(3040,2830) C15.2@3083.27,2830 ; C17.2@3083.27,3200 3081.46,3198.19 3081.46,3187.72 3079.37,3185.64 3095,3170.01 v3(3095,3155) ; C37.2@4765,2658.27 4765.98,2658.27 4767.8,2656.46 4767.8,2655.47 4793.27,2630 U8.3@4875,2630
  other v1: 3030,1860 3025,1955
  other v3: 2765,3900 2760,3980 2760,4065
5V: C20.2 C21.2 C28.2 C30.2 C32.2 C33.2 C36.2 C39.1 C41.1 D5.1 D6.1 D7.1 D8.1 D9.1 D10.1 D11.1 D12.1 D13.1 D14.1 D15.1 D16.1 D17.1 D18.1 D19.1 D20.1 D21.1 F1.2 R5.2 R15.2 R23.2 R25.2 R26.2 S2.3 TP2.1 U3.3 U4.7 U5.1 U9.8 U9.17 | length 9202.5
  Top Layer w10: S2.3@2170,4109.96 2239.96,4109.96 2345,4215 TP2.1@2430,4215 2470,4215 2500,4185 R5.2@2500,4136.73 ; C33.2@4025,2186.73 4156.42,2186.73 4169.69,2200 U4.7@4169.69,2248.07
  Top Layer w25: R15.2@2303.27,3595 2303.27,3673.27 v3(2305,3675) ; U9.8@2454.41,2013.7 2454.41,1890.59 2815,1530 2955,1530 3033.48,1451.52 3033.48,1417.5 3055.98,1395 v1(3090,1395) ; R26.2@3155,1611.73 v1(3155,1675) ; R23.2@3155,1931.73 v1(3155,1990) ; R25.2@3160,1291.73 v1(3160,1360) ; C28.2@3510,3570 C32.2@3625,3570 ; v2(3745,2920) D20.1@3835.53,2920 ; v2(3750,3110) D19.1@3840.53,3110 ; v2(3750,3305) D18.1@3840.53,3305 ; v2(3750,3500) D17.1@3840.53,3500 ; v2(3755,3690) D16.1@3845.53,3690 ; v2(3755,3880) D15.1@3845.53,3880 ; v2(3755,4075) D14.1@3845.53,4075 ; D21.1@3835.53,2725 v2(3745,2725) 3745,2580 3785,2540 v2(3965,2540) ; C33.2@4025,2186.73 v3(3961.73,2186.73) 3961.73,2038.27 4150,1850 v1(4380,1850) ; v2(4050,2725) D6.1@4140.53,2725 ; v2(4050,2920) D7.1@4140.53,2920 ; v2(4055,3110) D8.1@4145.53,3110 ; v2(4055,3305) D9.1@4145.53,3305 ; v2(4055,3500) D10.1@4145.53,3500 ; v2(4060,3690) D11.1@4150.53,3690 ; v2(4060,3880) D12.1@4150.53,3880 ; v2(4060,4075) D13.1@4150.53,4075 ; C36.2@4680,3363.46 4870.04,3363.46 U5.1@4875,3368.43
  Bottom Layer w25: C39.1@3019.11,1395.03 v1(3090,1395) ; C41.1@3020,1335 3050,1335 v1(3090,1295) ; v1(3090,1395) 3125,1395 v1(3160,1360) 3160,1670 v1(3155,1675) v1(3155,1990) 3275,2110 3885,2110 v3(3961.73,2186.73) ; v2(3965,2540) 3965,2191.35 3961.73,2188.09 v3(3961.73,2186.73) ; U5.1@4875,3368.43 4710,3203.43 4710,2585 4660,2535 4485,2535 4390,2440 4390,2375 4201.73,2186.73 v3(3961.73,2186.73)
  Bottom Layer w50: S2.3@2170,4109.96 2285.04,4109.96 2395,4000 2395,3725
  other v1: 4425,1850 4470,1850
  other v2: 3505,3515 3560,3515 3615,3515
  other v3: 2240,3675 2395,3675 2475,3675
12V: C4.2 C5.2 R4.2 S1.3 TP1.1 U2.2 | length 163
  Top Layer w10: R4.2@1251.73,4090 1280,4090 1300,4070 1300,4065 1310,4055 1315,4055
  Top Layer w35: C5.2@1325.42,3610 U2.2@1407.7,3610
A_SCL: R17.1 U1.12 U6.4 | length 3544.9
  Top Layer w6: U1.12@3110.87,2780.24 3110.87,2719.13 3125,2705 3125,2620 3265,2480 4300,2480 4405,2585 4405,3700 v2@4360,3745 ; v2(4520,3710) 4555,3710 4652.38,3612.62 U6.4@4875,3612.62 4792.9,3694.72 R17.1@4683.46,3694.72
  Bottom Layer w6: v2(4365,3735) 4365.49,3734.51 4365.49,3714.51 4395,3685 4495,3685 v2(4520,3710)
A_SDA: R18.1 U1.11 U6.2 | length 3420.1
  Top Layer w6: U1.11@3095.12,2780.24 3095.12,2714.88 3110,2700 3110,2595 3245,2460 4310,2460 4430,2580 v2(4430,3730) ; v2(4525,3810) 4855,3810 4865.26,3799.74 4830.52,3765 R18.1@4683.46,3765
  Bottom Layer w6: v2(4430,3730) 4509.48,3809.47
ADC_GAS: U1.39 U5.4 | length 3838.4
  Top Layer w6: v1(2940,3315) 2984.88,3270.12 U1.39@2984.88,3059.76 ; v2(3385,3315) 3385,3880 3470,3965 3580,3965 3745,4130 4325,4130 4395,4060 v2(4405,4060) ; v2(4630,3575) 4615,3560 4615,3175 4716.85,3073.15 U5.4@4875,3073.15
  Bottom Layer w6: v1(2940,3315) v2(3385,3315) v2@3390,3310 ; v2(4405,4060) 4590,4060 4630,4020 v2(4630,3575)
ADC_LUX: U1.38 U8.1 | length 4157.5
  Top Layer w6: v1@2975,3345 v1(2975,3340.63) 3000.63,3315 U1.38@3000.63,3059.76 ; v2(3339.37,3340.63) 3339.37,3894.37 3440,3995 3565,3995 3720,4150 v2(4370,4150) ; v2(4585,3555) 4585,3010 4765,2830 U8.1@4875,2830
  Bottom Layer w6: v1(2975,3340.63) v2(3339.37,3340.63) ; v2(4370,4150) 4275,4055 4275,3635 4355,3555 v2(4585,3555)
C_RX1: U1.6 U9.11 | length 1871.8
  Top Layer w6: U1.6@3016.38,2780.24 3016.38,2673.62 3030,2660 3030,2485 v1(3065,2450)
  Top Layer w25: U9.11@2572.53,1226.3 v1(2572.53,1307.46)
  Bottom Layer w10: v1(2572.53,1307.46) 2572.53,1887.54 2790,2105 2790,2335 2905,2450 v1(3065,2450)
C_TX1: U1.7 U9.10 | length 1979.1
  Top Layer w6: U1.7@3032.13,2780.24 3032.13,2687.87 3050,2670 3050,2545 v1(3115,2480)
  Top Layer w25: U9.10@2493.8,1226.3 v1(2493.8,1313.8) v1@2495,1315
  Bottom Layer w10: v1(2493.8,1313.8) 2493.8,1873.8 2745,2125 2745,2335 2890,2480 v1(3115,2480)
CC1: R12.2 USB1.4 | length 98.3
  Top Layer w6: v3(4670,1510) 4670.2,1509.8 USB1.4@4720,1509.8
  Bottom Layer w6: R12.2@4621.73,1510 v3(4670,1510)
CC2: R13.2 USB1.10 | length 94.5
  Top Layer w6: v3(4670,1625) 4672.91,1627.91 USB1.10@4720,1627.91
  Bottom Layer w6: R13.2@4626.73,1625 v3(4670,1625)
D_GAS: U1.27 U5.3 | length 3794.1
  Top Layer w6: U1.27@3179.76,3006.61 3216.61,3006.61 3255,3045 3255,3995 3335,4075 3555,4075 3705,4225 v2(4420,4225) ; v2(4685,3580) 4645,3540 4645,3235 4708.43,3171.57 U5.3@4875,3171.57
  Bottom Layer w6: v2(4420,4225) 4625,4225 4685,4165 v2(4685,3580)
D_WS2812: D6.4 U1.4 | length 2062.8
  Top Layer w6: U1.4@2984.88,2780.24 2983.5,2778.85 2983.5,2496.5 3075,2405 4295,2405 v3(4297.5,2402.5) ; v2(4295,2585) 4250,2585 4235,2600 4235,2689.03 4270.97,2725 D6.4@4278.94,2725 4283.37,2725 D6.4@4300,2741.63
  Bottom Layer w6: v2(4295,2585) 4295,2405 v3(4297.5,2402.5)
